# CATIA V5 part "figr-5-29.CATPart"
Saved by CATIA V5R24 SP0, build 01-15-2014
Part number: Part1
Bounding box of the stored display mesh (mm): x -100 to 100, y -100 to 100, z 0 to 57
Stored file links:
  D:\KAVITA\CATIA V5-6R2014 Project_ Kavita\CATIA V5-6R2014_partfiles\Partfiles\c05_catia_v5-6r2014_prt\figr-5-29.CATPart
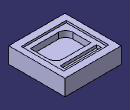
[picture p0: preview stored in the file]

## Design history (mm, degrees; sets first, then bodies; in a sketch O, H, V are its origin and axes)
Body1 (main body)
  Sketch1 on xy-plane, origin (0, 0, 0), H (1, 0, 0), V (0, 1, 0)
    line L1 (-100, 100) -> (100, 100)
    line L2 (100, 100) -> (100, -100)
    line L3 (100, -100) -> (-100, -100)
    line L4 (-100, -100) -> (-100, 100)
    axis line L5 (100, -100) -> (-100, 100)
    length L3 = 200
    length L2 = 200
    horizontal: L1 H, L3 H
    vertical: L2 V, L4 V
    midpoint: L5 O
  Pad1: profile Sketch1, direction (0, 0, 1), length 57
  Sketch2 on face of Pad1, origin (0, 0, 57), H (1, 0, 0), V (0, 1, 0)
    line L1 (-80.0557, 75.5465) -> (80.0557, 75.5465)
    line L2 (80.0557, 75.5465) -> (80.0557, -75.5465)
    line L3 (80.0557, -75.5465) -> (-80.0557, -75.5465)
    line L4 (-80.0557, -75.5465) -> (-80.0557, 75.5465)
    axis line L5 (80.0557, -75.5465) -> (-80.0557, 75.5465)
    line L6 (-62.1297, 30.1268) -> (-62.1297, -34.9955)
    arc A1 centre (-37.2362, -34.9955) radius 24.8935 from (-62.1297, -34.9955) to (-37.2362, -59.889) ccw
    line L7 (-37.2362, -59.889) -> (63.4636, -59.889)
    point P9 (63.4636, -59.889)
    line L8 (63.4636, -59.889) -> (63.4636, 3.0218)
    arc A2 centre (36.331, 3.0218) radius 27.1326 from (63.4636, 3.0218) to (35.1072, 30.1268) ccw
    line L9 (35.1072, 30.1268) -> (-62.1297, 30.1268)
    point P13 (-66.3387, 62.6022)
    line L10 (-66.3387, 62.6022) -> (63.4636, 62.6022)
    line L11 (63.4636, 62.6022) -> (63.4636, 45.9932)
    line L12 (63.4636, 45.9932) -> (-66.3387, 45.9932)
    line L13 (-66.3387, 45.9932) -> (-66.3387, 62.6022)
    point P15 (63.4636, 45.9932)
    horizontal: L1 H, L3 H, L9 H, L10 H, L12 H
    vertical: L2 V, L4 V, L6 V, L8 V, L11 V, L13 V
    midpoint: O L5
    tangency: A1 L6, L7 A1, A2 L5, A2 L8
    coincidence: P9 L5, P13 L5, P15 L8
  MultiPocket1: profile Sketch2, domains (length 17; length 28; length 7)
